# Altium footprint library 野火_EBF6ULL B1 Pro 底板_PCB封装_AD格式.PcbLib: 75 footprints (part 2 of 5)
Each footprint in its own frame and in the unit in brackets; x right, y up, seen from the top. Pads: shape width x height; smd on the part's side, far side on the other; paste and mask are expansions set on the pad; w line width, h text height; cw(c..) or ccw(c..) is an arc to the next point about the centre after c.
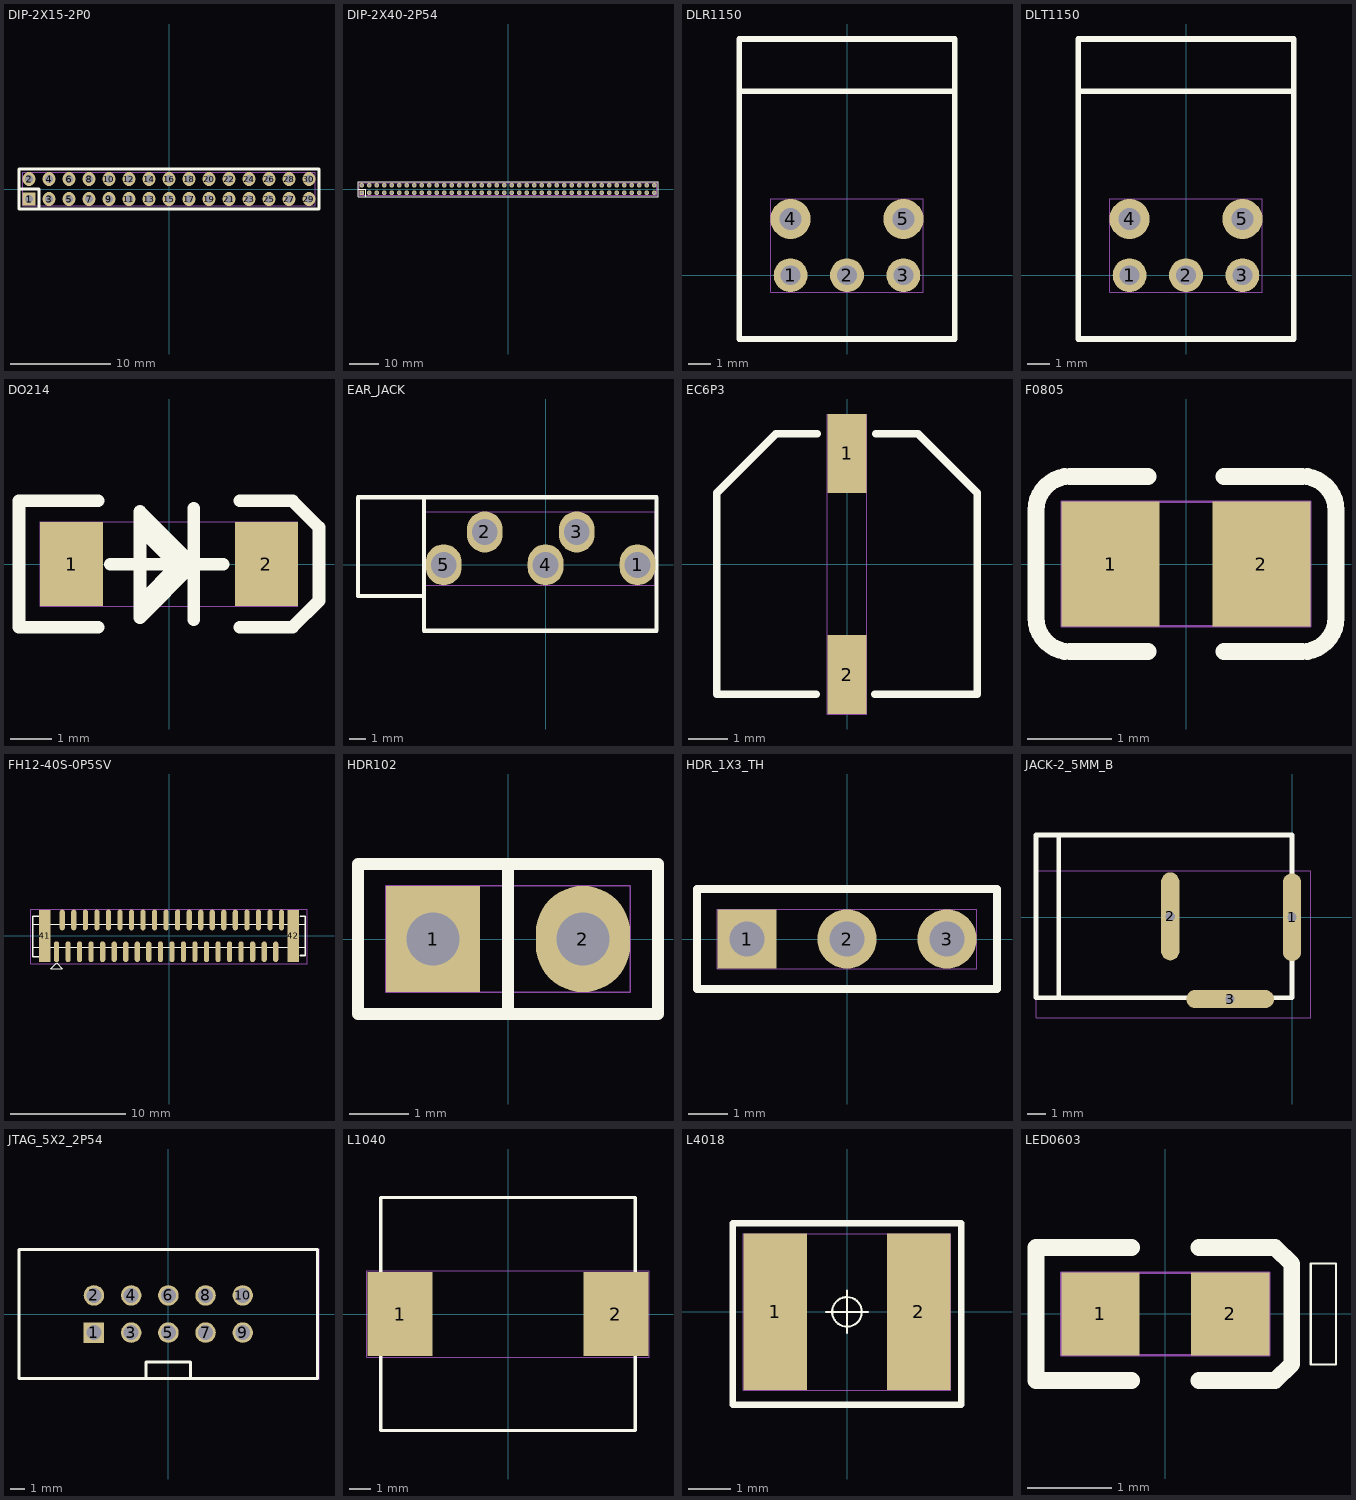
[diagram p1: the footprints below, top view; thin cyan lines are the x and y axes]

## DIP-2X15-2P0 [mil]
pads (30):
  rect 50x50 hole 32 mask+2: 1(-551.18,-39.37)
  oval 50x55 hole 32 mask+2: 2(-551.18,39.37) 3(-472.44,-39.37) 4(-472.44,39.37) 5(-393.7,-39.37) 6(-393.7,39.37) 7(-314.96,-39.37) 8(-314.96,39.37) 9(-236.22,-39.37) 10(-236.22,39.37) 11(-157.48,-39.37) 12(-157.48,39.37) 13(-78.74,-39.37) 14(-78.74,39.37) 15(0,-39.37) 16(0,39.37) 17(78.74,-39.37) 18(78.74,39.37) 19(157.48,-39.37) 20(157.48,39.37) 21(236.22,-39.37) 22(236.22,39.37) 23(314.96,-39.37) 24(314.96,39.37) 25(393.7,-39.37) 26(393.7,39.37) 27(472.44,-39.37) 28(472.44,39.37) 29(551.18,-39.37) 30(551.18,39.37)
Top Overlay:
  lines w10: -590.55,0 -511.81,0 -511.81,-78.74 ; -590.55,-78.74 590.55,-78.74 590.55,78.74 -590.55,78.74 -590.55,-78.74
Top Assembly:
  text "J38" at 57.25,25 h50
Mechanical 20:
  lines w1: -576.18,-66.87 576.18,-66.87 576.18,66.87 -576.18,66.87 -576.18,-66.87

## DIP-2X40-2P54 [mil]
pads (80):
  rect 62.99x62.99 hole 35.43 mask+2: 1(-1950,-50)
  round 62.99 hole 35.43 mask+2: 2(-1950,50) 3(-1850,-50) 4(-1850,50) 5(-1750,-50) 6(-1750,50) 7(-1650,-50) 8(-1650,50) 9(-1550,-50) 10(-1550,50) 11(-1450,-50) 12(-1450,50) 13(-1350,-50) 14(-1350,50) 15(-1250,-50) 16(-1250,50) 17(-1150,-50) 18(-1150,50) 19(-1050,-50) 20(-1050,50) 21(-950,-50) 22(-950,50) 23(-850,-50) 24(-850,50) 25(-750,-50) 26(-750,50) 27(-650,-50) 28(-650,50) 29(-550,-50) 30(-550,50) 31(-450,-50) 32(-450,50) 33(-350,-50) 34(-350,50) 35(-250,-50) 36(-250,50) 37(-150,-50) 38(-150,50) 39(-50,-50) 40(-50,50) 41(50,-50) 42(50,50) 43(150,-50) 44(150,50) 45(250,-50) 46(250,50) 47(350,-50) 48(350,50) 49(450,-50) 50(450,50) 51(550,-50) 52(550,50) 53(650,-50) 54(650,50) 55(750,-50) 56(750,50) 57(850,-50) 58(850,50) 59(950,-50) 60(950,50) 61(1050,-50) 62(1050,50) 63(1150,-50) 64(1150,50) 65(1250,-50) 66(1250,50) 67(1350,-50) 68(1350,50) 69(1450,-50) 70(1450,50) 71(1550,-50) 72(1550,50) 73(1650,-50) 74(1650,50) 75(1750,-50) 76(1750,50) 77(1850,-50) 78(1850,50) 79(1950,-50) 80(1950,50)
Top Overlay:
  lines w12: -2000,0 -1900,0 -1900,-100 ; -2000,-100 2000,-100 2000,100 -2000,100 -2000,-100
Top Assembly:
  text "CN5" at 65.11,25 h50
Mechanical 20:
  lines w1: -1981,-81 -1981,81 1981,81 1981,-81 -1981,-81

## DLR1150 [mil]
pads (5):
  round 60 hole 35 mask+2: 1(-100,0) 2(0,0) 3(100,0)
  round 70.87 hole 39.37 mask+2: 4(-100,99.61) 5(100,99.61)
Top Overlay:
  lines w10: -190.94,325.98 190.94,325.98 ; -190.94,325.98 -190.94,-112.99 190.94,-112.99 190.94,325.98 ; -190.94,325.98 -190.94,418.5 190.94,418.5 190.94,325.98
Top Assembly:
  text "CN8" at -65.11,-25 h50
Mechanical 20:
  lines w1: -135.43,-30 135.43,-30 135.43,135.04 -135.43,135.04 -135.43,-30

## DLT1150 [mil]
pads (5):
  round 60 hole 35 mask+2: 1(-100,0) 2(0,0) 3(100,0)
  round 70.87 hole 39.37 mask+2: 4(-100,99.61) 5(100,99.61)
Top Overlay:
  lines w10: -190.94,325.98 -190.94,418.5 190.94,418.5 190.94,325.98 ; -190.94,325.98 -190.94,-112.99 190.94,-112.99 190.94,325.98 ; -190.94,325.98 190.94,325.98
Top Assembly:
  text "CN12" at -83.44,-25 h50
Mechanical 20:
  lines w1: -135.43,-30 135.43,-30 135.43,135.04 -135.43,135.04 -135.43,-30

## DO214 [mil]
pads (2):
  rect 60x80 smd mask+2: 1(-92.5,0) 2(92.5,0)
Top Overlay:
  lines w1: -27.58,-25.06 -27.58,22.87 -1.5,22.87 -1.5,-25.06 -27.58,-25.06
  lines w12: -67.5,-60 -142.5,-60 -142.5,60 -67.5,60 ; -55.58,-0.13 51.42,-0.13 ; -27.58,33.87 7.79,-1.51 -25.84,-35.13 ; 23.42,-53.13 23.42,52.87 ; 67.5,-60 117.42,-60 142.5,-34.92 142.5,34.87 117.37,60 67.5,60 ; -27.58,-51.13 23.42,-0.13 23.42,-1.13 -27.58,49.87 -27.58,-51.13
Top Assembly:
  text "D2" at 38.93,25 h50
Mechanical 20:
  lines w1: -122.5,-40 122.5,-40 122.5,40 -122.5,40 -122.5,-40

## EAR_JACK [mil]
pads (5):
  oval 86x98 hole 62 mask+2: 1(220.47,0) 2(-145.67,78.74) 3(74.8,78.74) 4(0,0) 5(-244.1,0)
Top Overlay:
  lines w10: -294.49,-75.03 -449.49,-75.03 -449.49,161.97 -294.49,161.97 ; -291.49,-158.03 -291.49,161.97 265.51,161.97 265.51,-158.03 -291.49,-158.03
Top Assembly:
  text "J32" at 57.25,25 h50
Mechanical 20:
  lines w1: -287.1,-49 263.47,-49 263.47,127.74 -287.1,127.74 -287.1,-49

## EC6P3 [mm]
pads (2):
  rect 1x2 smd mask+0.051: 1(0,2.8) 2(0,-2.8)
Top Overlay:
  lines w0.2: -0.787,-3.3 -3.3,-3.3 -3.3,1.8 -1.8,3.3 -0.762,3.3 ; 0.711,-3.3 3.3,-3.3 3.3,1.8 1.8,3.3 0.737,3.3
Top Assembly:
  text "C93" at -1.621,-0.635 h1.27
Mechanical 20:
  lines w0.025: -0.5,-3.8 0.5,-3.8 0.5,3.8 -0.5,3.8 -0.5,-3.8

## F0805 [mm]
pads (2):
  rect 1.16x1.47 smd mask+0.051: 1(-0.89,0) 2(0.89,0)
Top Overlay:
  lines w0.2: -0.45,-1.035 -1.37,-1.035 cw(c-1.37,-0.635) -1.77,-0.635 -1.77,0.635 cw(c-1.37,0.635) -1.37,1.035 -0.45,1.035 ; 0.45,-1.035 1.37,-1.035 ccw(c1.37,-0.635) 1.77,-0.635 1.77,0.635 ccw(c1.37,0.635) 1.37,1.035 0.45,1.035
Top Assembly:
  text "F1" at -0.617,-0.635 h1.27
Mechanical 20:
  lines w0.025: -1.47,-0.735 1.47,-0.735 1.47,0.735 -1.47,0.735 -1.47,-0.735

## FH12-40S-0P5SV [mil]
height 196
pads (42):
  oval 17.72x70.87 smd mask+1.97: 1(-383.85,-54.13) 2(-364.17,54.13) 3(-344.48,-54.13) 4(-324.8,54.13) 5(-305.11,-54.13) 6(-285.43,54.13) 7(-265.74,-54.13) 8(-246.06,54.13) 9(-226.37,-54.13) 10(-206.69,54.13) 11(-187,-54.13) 12(-167.32,54.13) 13(-147.63,-54.13) 14(-127.96,54.13) 15(-108.26,-54.13) 16(-88.59,54.13) 17(-68.89,-54.13) 18(-49.22,54.13) 19(-29.52,-54.13) 20(-9.85,54.13) 21(9.85,-54.13) 22(29.52,54.13) 23(49.22,-54.13) 24(68.89,54.13) 25(88.59,-54.13) 26(108.26,54.13) 27(127.96,-54.13) 28(147.63,54.13) 29(167.33,-54.13) 30(187,54.13) 31(206.7,-54.13) 32(226.37,54.13) 33(246.07,-54.13) 34(265.74,54.13) 35(285.44,-54.13) 36(305.11,54.13) 37(324.81,-54.13) 38(344.48,54.13) 39(364.17,-54.13) 40(383.85,54.13)
  rect 39.37x177.17 smd mask+1.97: 41(-423.24,0) 42(423.24,0)
Top Overlay:
  lines w1: -464.56,-39.37 -464.56,39.37 464.56,39.37 464.56,-39.37 -464.56,-39.37 ; -403.7,-111.81 -383.7,-91.81 -363.7,-111.81 -403.7,-111.81
  lines w6: -444.89,-70.87 -464.56,-70.87 -464.56,66.93 -444.89,66.93 ; 448.81,-66.93 464.56,-66.93 464.56,66.93 448.81,66.93
Top Assembly:
  text "J16" at 52.14,25 h50
Mechanical 20:
  lines w1: -472.44,-94.49 -472.44,90.55 472.44,90.55 472.44,-94.49 -472.44,-94.49

## HDR102 [mil]
pads (2):
  rect 62.99x70.87 / inner oval 62.99x70.87 / far side rect 62.99x70.87 hole 35.43 mask+1.97: 1(-50,0)
  oval 62.99x70.87 hole 35.43 mask+1.97: 2(50,0)
Top Overlay:
  lines w8: 0,-50 0,50 ; -100,-50 100,-50 100,50 -100,50 -100,-50
Top Assembly:
  text "J30" at -57.25,-25 h50
Mechanical 20:
  lines w1: -81.5,-35.43 81.5,-35.43 81.5,35.43 -81.5,35.43 -81.5,-35.43

## HDR_1X3_TH [mil]
height 47
pads (3):
  rect 59.06x59.06 hole 35.43 mask+2: 1(-100,0)
  round 59.06 hole 35.43 mask+2: 2(0,0) 3(100,0)
Top Overlay:
  lines w7.87: -150,-50 150,-50 150,50 -150,50 -150,-50
Top Assembly:
  text "J37" at -57.25,-25 h50
Mechanical 20:
  lines w1: -129.53,-29.53 129.53,-29.53 129.53,29.53 -129.53,29.53 -129.53,-29.53

## JACK-2_5MM_B [mm]
pads (3):
  oval 1x4.81 / inner oval 1x4.81 / far side oval 2x4.81 hole 0.5 mask+0.05: 1(0,0) 2(-6.659,0.046)
  oval 4.81x1 / inner oval 4.81x1 / far side oval 4.81x2 hole 0.5 mask+0.05: 3(-3.383,-4.475)
Top Overlay:
  lines w0.254: -12.755,-4.348 -12.755,4.501 ; -14,-4.399 -14,4.501 0,4.501 0,-4.399 -14,-4.399
Top Assembly:
  text "JACK1" at -2.446,-0.635 h1.27
Mechanical 20:
  lines w0.025: -14,-5.491 1.016,-5.491 1.016,2.535 -14,2.535 -14,-5.491

## JTAG_5X2_2P54 [mil]
pads (10):
  rect 55x55 / inner round 55 / far side rect 55x55 hole 40 mask+2.5: 1(-200,-50)
  round 55 hole 40 mask+2.5: 2(-200,50) 3(-100,-50) 4(-100,50) 5(0,-50) 6(0,50) 7(100,-50) 8(100,50) 9(200,-50) 10(200,50)
Top Overlay:
  lines w8: -60,-170 -60,-130 ; -60,-129.37 60,-129.37 ; 60,-170 60,-130 ; -401.57,-173 401.57,-173 401.57,173 -401.57,173 -401.57,-173
Top Assembly:
  text "J1" at -24.29,-25 h50
Mechanical 20:
  lines w1: -400,-175 405,-175 405,175 -400,175 -400,-175

## L1040 [mm]
height 5.283
pads (2):
  rect 3x3.9 smd mask+0.05: 1(-5,0) 2(5,0)
Top Overlay:
  lines w0.152: -5.9,-5.4 5.9,-5.4 5.9,5.4 -5.9,5.4 -5.9,-5.4
Top Assembly:
  text "L1" at 0.584,0.635 h1.27
Mechanical 20:
  lines w0.025: -6.55,-2 6.55,-2 6.55,2 -6.55,2 -6.55,-2

## L4018 [mm]
height 5.283
pads (2):
  rect 1.5x3.7 smd mask+0.05: 1(-1.7,0) 2(1.7,0)
Top Overlay:
  circle w0.05: c0,0 r0.35
  lines w0.05: -0.5,0 0.5,0 ; 0,-0.5 0,0.5
  lines w0.152: -2.7,-2.2 2.7,-2.2 2.7,2.1 -2.7,2.1 -2.7,-2.2
Top Assembly:
  text "L2" at -0.856,-0.635 h1.27
Mechanical 20:
  lines w0.025: -2.45,-1.85 2.45,-1.85 2.45,1.85 -2.45,1.85 -2.45,-1.85

## LED0603 [mil]
pads (2):
  rect 36.61x38.58 smd mask+1.97: 1(-30.31,0) 2(30.32,0)
Top Overlay:
  lines w1: 67.91,-23.62 67.91,23.62 79.73,23.62 79.73,-23.62 67.91,-23.62
  lines w7.87: -15.75,-31.1 -60.43,-31.1 -60.43,31.1 -15.75,31.1 ; 15.75,-31.1 51.18,-31.1 59.06,-23.5 59.06,23.5 51.18,31.1 15.75,31.1
Top Assembly:
  text "D7" at 38.93,25 h50
Mechanical 20:
  lines w1: -48.62,-19.29 48.62,-19.29 48.62,19.29 -48.62,19.29 -48.62,-19.29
